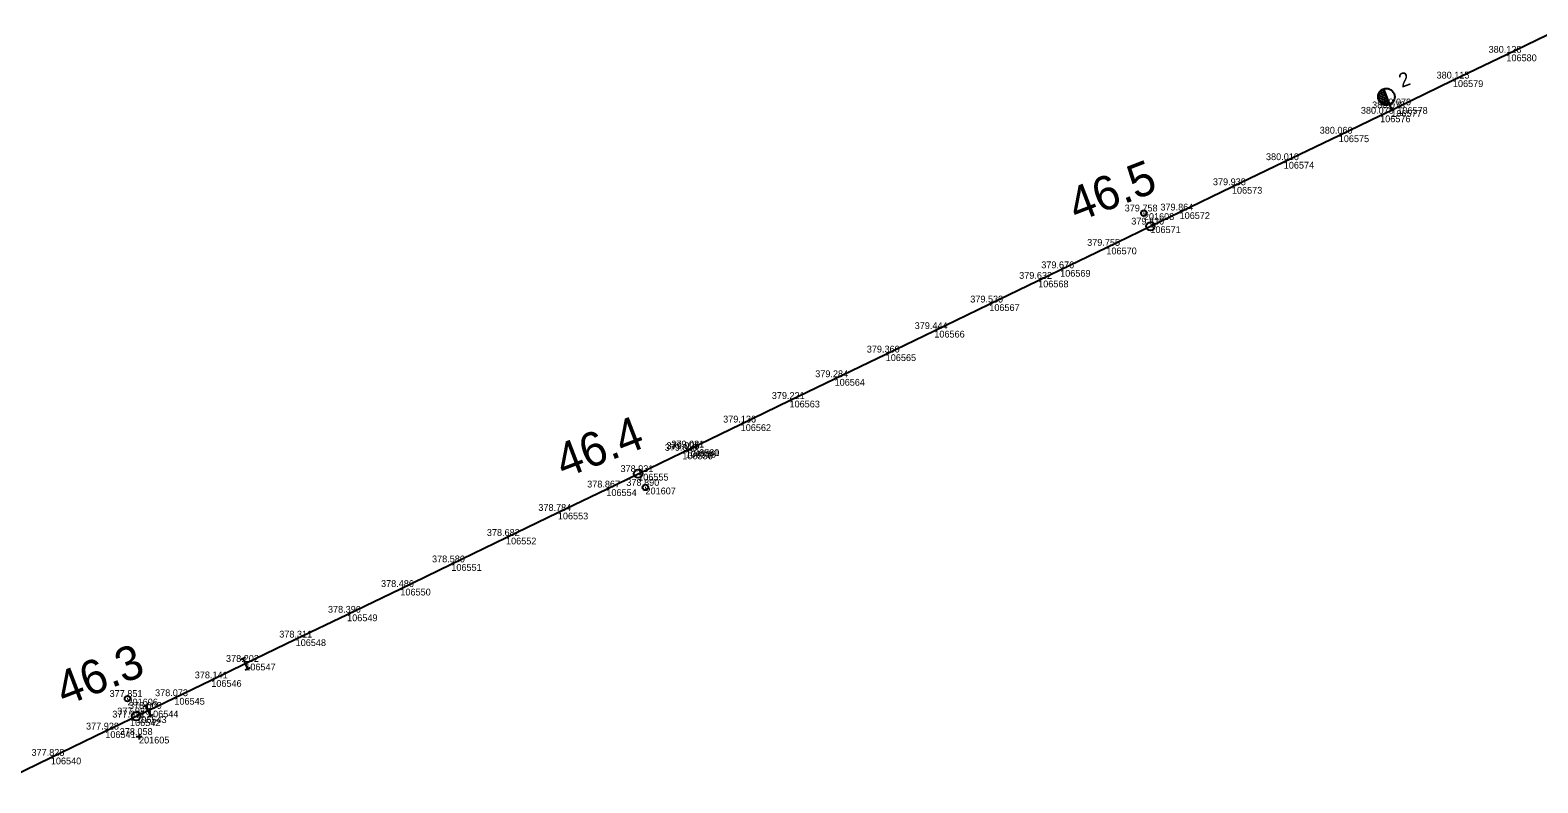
# Model space of a CAD drawing. Extents: x -545715 to -485912, y -1154994 to -1140055.
# Drawn here: x -509965.9 to -509700, y -1143360.9 to -1143228.2 of the extents above; entities that cross this region are included whole.
import ezdxf

# ---------------------------------------------------------------- set-up
doc = ezdxf.new("R2010")
doc.units = 0
for name, color, linetype in [('Vrstva 1', 7, 'Continuous'), ('Vrstva 2', 7, 'Continuous'), ('Vrstva 3', 7, 'Continuous'), ('Vrstva 4', 7, 'Continuous'), ('Vrstva 60', 7, 'Continuous'), ('Vrstva 61', 7, 'Continuous'), ('Vrstva 7', 7, 'Continuous')]:
    doc.layers.add(name, color=color, linetype=linetype)

msp = doc.modelspace()

# ---------------------------------------------------------------- linework, layer by layer
at = {"layer": 'Vrstva 1'}
for p, q in [((-509705.55, -1143232.44), (-509696.67, -1143228.16)), ((-509714.98, -1143236.99), (-509705.55, -1143232.44)), ((-509724.78, -1143241.72), (-509714.98, -1143236.99)), ((-509727.81, -1143243.19), (-509725.83, -1143242.24)), ((-509725.83, -1143242.24), (-509724.78, -1143241.72)), ((-509735.11, -1143246.7), (-509727.81, -1143243.19)), ((-509744.81, -1143251.37), (-509735.11, -1143246.7)), ((-509753.95, -1143255.79), (-509744.81, -1143251.37)), ((-509763.18, -1143260.25), (-509753.95, -1143255.79)), ((-509768.33, -1143262.73), (-509763.18, -1143260.25)), ((-509776.09, -1143266.48), (-509768.33, -1143262.73)), ((-509784.24, -1143270.43), (-509776.09, -1143266.48)), ((-509788.12, -1143272.3), (-509784.24, -1143270.43)), ((-509796.74, -1143276.47), (-509788.12, -1143272.3)), ((-509806.43, -1143281.15), (-509796.74, -1143276.47)), ((-509815, -1143285.28), (-509806.43, -1143281.15)), ((-509824.02, -1143289.64), (-509815, -1143285.28)), ((-509831.97, -1143293.47), (-509824.02, -1143289.64)), ((-509840.58, -1143297.63), (-509831.97, -1143293.47)), ((-509849.69, -1143302.03), (-509840.58, -1143297.63)), ((-509858.65, -1143306.36), (-509850.87, -1143302.61)), ((-509850.87, -1143302.61), (-509849.69, -1143302.03)), ((-509864.27, -1143309.08), (-509858.65, -1143306.36)), ((-509872.82, -1143313.21), (-509864.27, -1143309.08)), ((-509881.96, -1143317.62), (-509872.82, -1143313.21)), ((-509891.61, -1143322.28), (-509881.96, -1143317.62)), ((-509900.59, -1143326.63), (-509891.61, -1143322.28)), ((-509909.98, -1143331.16), (-509900.59, -1143326.63)), ((-509919.06, -1143335.54), (-509909.98, -1143331.16)), ((-509927.94, -1143339.83), (-509919.06, -1143335.54)), ((-509933.94, -1143342.73), (-509927.94, -1143339.83)), ((-509940.44, -1143345.87), (-509933.94, -1143342.73)), ((-509945.09, -1143348.11), (-509940.44, -1143345.87)), ((-509948.26, -1143349.64), (-509947.17, -1143349.11)), ((-509947.17, -1143349.11), (-509945.09, -1143348.11)), ((-509962.23, -1143356.39), (-509952.63, -1143351.75)), ((-509952.63, -1143351.75), (-509948.26, -1143349.64)), ((-509971.45, -1143360.85), (-509962.23, -1143356.39))]:
    msp.add_line(p, q, dxfattribs=at)
at = {"layer": 'Vrstva 2'}
for p, q in [((-509726.34, -1143240.87), (-509728.16, -1143240.05)), ((-509726.53, -1143240.38), (-509728.15, -1143239.64)), ((-509726.72, -1143239.88), (-509728.03, -1143239.28)), ((-509726.9, -1143239.38), (-509727.83, -1143238.96)), ((-509727.09, -1143238.89), (-509727.52, -1143238.69)), ((-509726.19, -1143241.27), (-509727.22, -1143238.53)), ((-509727.22, -1143238.53), (-509726.19, -1143241.27)), ((-509726.3, -1143241.3), (-509728.03, -1143240.52)), ((-509726.19, -1143241.27), (-509725.83, -1143242.24)), ((-509726.19, -1143241.27), (-509726.19, -1143241.27))]:
    msp.add_line(p, q, dxfattribs=at)
msp.add_circle((-509726.71, -1143239.89), 1.46, dxfattribs=at)
msp.add_arc((-509726.71, -1143239.9), 1.46, 110.6292, 290.5901, dxfattribs=at)
at = {"layer": 'Vrstva 3'}
for p, q in [((-509928.81, -1143339.13), (-509927.91, -1143338.71)), ((-509928.36, -1143338.92), (-509927.52, -1143340.73)), ((-509927.97, -1143340.94), (-509927.06, -1143340.52)), ((-509945.97, -1143347.42), (-509945.06, -1143347)), ((-509945.52, -1143347.21), (-509944.67, -1143349.02)), ((-509945.12, -1143349.23), (-509944.22, -1143348.81))]:
    msp.add_line(p, q, dxfattribs=at)
at = {"layer": 'Vrstva 4'}
msp.add_line((-509940.44, -1143345.87), (-509933.94, -1143342.73), dxfattribs=at)
at = {"layer": 'Vrstva 60'}
for p, q in [((-509705.55, -1143232.44), (-509705.55, -1143232.44)), ((-509714.98, -1143236.99), (-509714.98, -1143236.99)), ((-509725.83, -1143242.24), (-509725.83, -1143242.24)), ((-509724.78, -1143241.72), (-509724.78, -1143241.72)), ((-509727.81, -1143243.19), (-509727.81, -1143243.19)), ((-509735.11, -1143246.7), (-509735.11, -1143246.7)), ((-509744.81, -1143251.37), (-509744.81, -1143251.37)), ((-509753.95, -1143255.79), (-509753.95, -1143255.79)), ((-509769.48, -1143260.43), (-509769.48, -1143260.43)), ((-509763.18, -1143260.25), (-509763.18, -1143260.25)), ((-509768.33, -1143262.73), (-509768.33, -1143262.73)), ((-509776.09, -1143266.48), (-509776.09, -1143266.48)), ((-509784.24, -1143270.43), (-509784.24, -1143270.43)), ((-509788.12, -1143272.3), (-509788.12, -1143272.3)), ((-509796.74, -1143276.47), (-509796.74, -1143276.47)), ((-509806.43, -1143281.15), (-509806.43, -1143281.15)), ((-509815, -1143285.28), (-509815, -1143285.28)), ((-509824.02, -1143289.64), (-509824.02, -1143289.64)), ((-509831.97, -1143293.47), (-509831.97, -1143293.47)), ((-509840.58, -1143297.63), (-509840.58, -1143297.63)), ((-509850.87, -1143302.61), (-509850.87, -1143302.61)), ((-509850.87, -1143302.61), (-509850.87, -1143302.61)), ((-509850.3, -1143302.33), (-509850.3, -1143302.33)), ((-509850.25, -1143302.31), (-509850.25, -1143302.31)), ((-509849.7, -1143302.04), (-509849.7, -1143302.04)), ((-509849.69, -1143302.03), (-509849.69, -1143302.03)), ((-509858.65, -1143306.36), (-509858.65, -1143306.36)), ((-509864.27, -1143309.08), (-509864.27, -1143309.08)), ((-509857.37, -1143308.78), (-509857.37, -1143308.78)), ((-509872.82, -1143313.21), (-509872.82, -1143313.21)), ((-509881.96, -1143317.62), (-509881.96, -1143317.62)), ((-509891.61, -1143322.28), (-509891.61, -1143322.28)), ((-509900.59, -1143326.63), (-509900.59, -1143326.63)), ((-509909.98, -1143331.16), (-509909.98, -1143331.16)), ((-509919.06, -1143335.54), (-509919.06, -1143335.54)), ((-509927.94, -1143339.83), (-509927.94, -1143339.83)), ((-509933.94, -1143342.73), (-509933.94, -1143342.73)), ((-509948.71, -1143346.01), (-509948.71, -1143346.01)), ((-509940.44, -1143345.87), (-509940.44, -1143345.87)), ((-509947.17, -1143349.11), (-509947.17, -1143349.11)), ((-509945.09, -1143348.11), (-509945.09, -1143348.11)), ((-509952.63, -1143351.75), (-509952.63, -1143351.75)), ((-509948.26, -1143349.64), (-509948.26, -1143349.64)), ((-509946.68, -1143352.71), (-509946.68, -1143352.71)), ((-509962.23, -1143356.39), (-509962.23, -1143356.39))]:
    msp.add_line(p, q, dxfattribs=at)
at = {"layer": 'Vrstva 7'}
for p, q in [((-509769.53, -1143260.43), (-509769.43, -1143260.43)), ((-509857.42, -1143308.78), (-509857.32, -1143308.78)), ((-509948.76, -1143346.01), (-509948.66, -1143346.01)), ((-509947.18, -1143352.71), (-509946.18, -1143352.71)), ((-509946.68, -1143352.21), (-509946.68, -1143353.21))]:
    msp.add_line(p, q, dxfattribs=at)
for centre, radius in [((-509769.48, -1143260.43), 0.5), ((-509768.33, -1143262.73), 0.75), ((-509858.65, -1143306.36), 0.75), ((-509857.37, -1143308.78), 0.5), ((-509948.71, -1143346.01), 0.5), ((-509947.17, -1143349.11), 0.75)]:
    msp.add_circle(centre, radius, dxfattribs=at)

# ---------------------------------------------------------------- texts
at = {"layer": 'Vrstva 2'}
msp.add_text('2', height=2.5, rotation=20.5807, dxfattribs=at).set_placement((-509723.99, -1143238.35))
at = {"layer": 'Vrstva 60'}
for s, p in [('106580', (-509705.55, -1143233.64)), ('106579', (-509714.98, -1143238.19)), ('106577', (-509725.83, -1143243.44)), ('106578', (-509724.78, -1143242.92)), ('106576', (-509727.81, -1143244.39)), ('106575', (-509735.11, -1143247.9)), ('106574', (-509744.81, -1143252.57)), ('106573', (-509753.95, -1143256.99)), ('201608', (-509769.48, -1143261.62)), ('106572', (-509763.18, -1143261.45)), ('106571', (-509768.33, -1143263.93)), ('106570', (-509776.09, -1143267.68)), ('106569', (-509784.24, -1143271.63)), ('106568', (-509788.12, -1143273.5)), ('106567', (-509796.74, -1143277.67)), ('106566', (-509806.43, -1143282.35)), ('106565', (-509815, -1143286.49)), ('106564', (-509824.02, -1143290.84)), ('106563', (-509831.97, -1143294.67)), ('106562', (-509840.58, -1143298.83)), ('106556', (-509850.87, -1143303.81)), ('106557', (-509850.87, -1143303.81)), ('106558', (-509850.3, -1143303.53)), ('106559', (-509850.25, -1143303.51)), ('106560', (-509849.7, -1143303.24)), ('106561', (-509849.69, -1143303.23)), ('106555', (-509858.65, -1143307.56)), ('106554', (-509864.27, -1143310.28)), ('201607', (-509857.37, -1143309.99)), ('106553', (-509872.82, -1143314.41)), ('106552', (-509881.96, -1143318.82)), ('106551', (-509891.61, -1143323.48)), ('106550', (-509900.59, -1143327.82)), ('106549', (-509909.98, -1143332.36)), ('106548', (-509919.06, -1143336.74)), ('106547', (-509927.94, -1143341.03)), ('106546', (-509933.94, -1143343.93)), ('201606', (-509948.71, -1143347.21)), ('106545', (-509940.44, -1143347.07)), ('106543', (-509947.17, -1143350.31)), ('106544', (-509945.09, -1143349.31)), ('106541', (-509952.63, -1143352.95)), ('106542', (-509948.26, -1143350.84)), ('201605', (-509946.68, -1143353.91)), ('106540', (-509962.23, -1143357.59))]:
    msp.add_text(s, height=1.2, dxfattribs=at).set_placement(p)
at = {"layer": 'Vrstva 61'}
for s, p in [('380.128', (-509708.69, -1143232.14)), ('380.115', (-509717.86, -1143236.69)), ('380.079', (-509728.15, -1143241.42)), ('380.078', (-509731.21, -1143242.89)), ('380.078', (-509729.23, -1143241.94)), ('380.060', (-509738.47, -1143246.4)), ('380.010', (-509747.94, -1143251.07)), ('379.938', (-509757.3, -1143255.49)), ('379.864', (-509766.56, -1143259.95)), ('379.758', (-509772.86, -1143260.12)), ('379.830', (-509771.7, -1143262.43)), ('379.755', (-509779.48, -1143266.18)), ('379.676', (-509787.57, -1143270.13)), ('379.632', (-509791.47, -1143272)), ('379.539', (-509800.09, -1143276.17)), ('379.444', (-509809.89, -1143280.85)), ('379.360', (-509818.34, -1143284.99)), ('379.284', (-509827.43, -1143289.34)), ('379.221', (-509835.09, -1143293.17)), ('379.136', (-509843.67, -1143297.33)), ('379.019', (-509853.96, -1143302.31)), ('379.019', (-509853.96, -1143302.31)), ('379.025', (-509853.68, -1143302.03)), ('379.025', (-509853.63, -1143302.01)), ('379.031', (-509852.82, -1143301.74)), ('379.031', (-509852.8, -1143301.73)), ('378.931', (-509861.77, -1143306.06)), ('378.867', (-509867.65, -1143308.78)), ('378.890', (-509860.74, -1143308.49)), ('378.784', (-509876.26, -1143312.91)), ('378.682', (-509885.34, -1143317.32)), ('378.580', (-509895.01, -1143321.98)), ('378.486', (-509904, -1143326.32)), ('378.390', (-509913.36, -1143330.86)), ('378.311', (-509921.95, -1143335.24)), ('378.202', (-509931.34, -1143339.53)), ('378.141', (-509936.85, -1143342.43)), ('377.851', (-509951.87, -1143345.71)), ('378.073', (-509943.85, -1143345.57)), ('377.971', (-509951.39, -1143349.34)), ('377.986', (-509950.53, -1143348.81)), ('378.009', (-509948.46, -1143347.81)), ('377.928', (-509956.02, -1143351.45)), ('378.058', (-509950.08, -1143352.41)), ('377.828', (-509965.64, -1143356.09))]:
    msp.add_text(s, height=1.2, dxfattribs=at).set_placement(p)
at = {"layer": 'Vrstva 7'}
for s, p in [('46.5', (-509781.35, -1143262.07)), ('46.4', (-509871.79, -1143307.22)), ('46.3', (-509959.88, -1143347.37))]:
    msp.add_text(s, height=6, rotation=21.0655, dxfattribs=at).set_placement(p)

doc.saveas('drawing.dxf')
